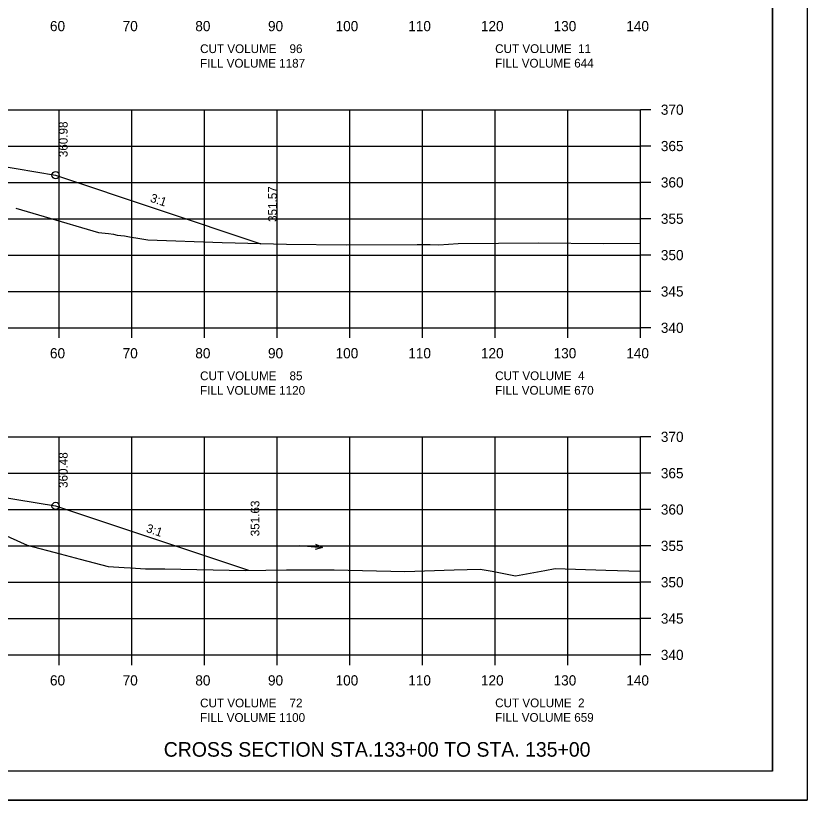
# Model space of a CAD drawing. Extents: x 1374859 to 1376773, y 382242 to 389804.
# Drawn here: x 1376188.6 to 1376297.5, y 385228.5 to 385336.4 of the extents above; entities that cross this region are included whole.
import ezdxf

# ---------------------------------------------------------------- set-up
doc = ezdxf.new("R2010")
doc.units = 0
for name, color, linetype in [('R_Axis', 7, 'Continuous'), ('R_Axis Annot', 7, 'Continuous'), ('R_Border', 7, 'Continuous'), ('R_Draft', 7, 'Continuous'), ('R_Exist Surface', 7, 'Continuous'), ('R_Fin Surface', 7, 'Continuous'), ('R_Grid', 7, 'Continuous'), ('R_No Plot', 7, 'Continuous'), ('R_Water Annot', 7, 'Continuous'), ('R_Xsect Elev', 7, 'Continuous'), ('R_Xsect Slope', 7, 'Continuous')]:
    doc.layers.add(name, color=color, linetype=linetype)

msp = doc.modelspace()

# ---------------------------------------------------------------- linework, layer by layer
at = {"layer": 'R_Axis'}
for p, q in [((1376274.57, 385293.45), (1376274.57, 385323.45)), ((1376275.97, 385323.45), (1376274.57, 385323.45)), ((1376275.97, 385318.45), (1376274.57, 385318.45)), ((1376275.97, 385313.45), (1376274.57, 385313.45)), ((1376275.97, 385308.45), (1376274.57, 385308.45)), ((1376275.97, 385303.45), (1376274.57, 385303.45)), ((1376275.97, 385298.45), (1376274.57, 385298.45)), ((1375994.57, 385293.45), (1376274.57, 385293.45)), ((1376194.57, 385292.05), (1376194.57, 385293.45)), ((1376204.57, 385292.05), (1376204.57, 385293.45)), ((1376214.57, 385292.05), (1376214.57, 385293.45)), ((1376224.57, 385292.05), (1376224.57, 385293.45)), ((1376234.57, 385292.05), (1376234.57, 385293.45)), ((1376244.57, 385292.05), (1376244.57, 385293.45)), ((1376254.57, 385292.05), (1376254.57, 385293.45)), ((1376264.57, 385292.05), (1376264.57, 385293.45)), ((1376274.57, 385292.05), (1376274.57, 385293.45)), ((1376275.97, 385293.45), (1376274.57, 385293.45)), ((1376274.57, 385248.45), (1376274.57, 385278.45)), ((1376275.97, 385278.45), (1376274.57, 385278.45)), ((1376275.97, 385273.45), (1376274.57, 385273.45)), ((1376275.97, 385268.45), (1376274.57, 385268.45)), ((1376275.97, 385263.45), (1376274.57, 385263.45)), ((1376275.97, 385258.45), (1376274.57, 385258.45)), ((1376275.97, 385253.45), (1376274.57, 385253.45)), ((1375994.57, 385248.45), (1376274.57, 385248.45)), ((1376194.57, 385247.05), (1376194.57, 385248.45)), ((1376204.57, 385247.05), (1376204.57, 385248.45)), ((1376214.57, 385247.05), (1376214.57, 385248.45)), ((1376224.57, 385247.05), (1376224.57, 385248.45)), ((1376234.57, 385247.05), (1376234.57, 385248.45)), ((1376244.57, 385247.05), (1376244.57, 385248.45)), ((1376254.57, 385247.05), (1376254.57, 385248.45)), ((1376264.57, 385247.05), (1376264.57, 385248.45)), ((1376274.57, 385247.05), (1376274.57, 385248.45)), ((1376275.97, 385248.45), (1376274.57, 385248.45))]:
    msp.add_line(p, q, dxfattribs=at)
at = {"layer": 'R_Border'}
for q in [(1376292.75, 385437.91), (1375976.57, 385232.45)]:
    msp.add_line((1376292.75, 385232.45), q, dxfattribs=at)
at = {"layer": 'R_Exist Surface'}
for points in [[(1376188.61, 385309.91), (1376192.52, 385308.77), (1376199.99, 385306.57), (1376201.36, 385306.41), (1376202.05, 385306.33), (1376202.07, 385306.32), (1376202.54, 385306.2), (1376203.57, 385306.09), (1376204.27, 385305.94), (1376205.66, 385305.72), (1376206.78, 385305.54), (1376217.01, 385305.16), (1376225.87, 385304.93), (1376234.08, 385304.88), (1376243.83, 385304.91), (1376245.61, 385304.89), (1376246.84, 385304.88), (1376249.46, 385305.03), (1376260.6, 385305.12), (1376269.44, 385305.04), (1376274.57, 385305.07)], [(1376178.83, 385268.64), (1376190.16, 385263.53), (1376194.72, 385262.35), (1376197.47, 385261.63), (1376201.3, 385260.59), (1376203.51, 385260.47), (1376204.41, 385260.42), (1376206.47, 385260.31), (1376209.11, 385260.27), (1376220.16, 385260.08), (1376225.87, 385260.17), (1376232.41, 385260.16), (1376242.14, 385259.91), (1376248.94, 385260.15), (1376252.52, 385260.25), (1376254.14, 385259.96), (1376257.38, 385259.33), (1376261.4, 385260.07), (1376262.84, 385260.34), (1376269.8, 385260.13), (1376274.57, 385259.98)]]:
    msp.add_lwpolyline(points, dxfattribs=at)
at = {"layer": 'R_Fin Surface'}
for points in [[(1376049.29, 385304.98), (1376056.66, 385302.52), (1376075.09, 385308.66), (1376083.13, 385310), (1376097.09, 385312.33), (1376105.09, 385312.95), (1376134.59, 385315.22), (1376164.09, 385317.49), (1376172.09, 385318.1), (1376185.9, 385315.8), (1376194.09, 385314.44), (1376222.34, 385305.02)], [(1376051.43, 385259.78), (1376058.18, 385257.53), (1376075.09, 385263.16), (1376083.13, 385264.5), (1376097.09, 385266.83), (1376105.09, 385267.45), (1376134.59, 385269.72), (1376164.09, 385271.99), (1376172.09, 385272.6), (1376185.9, 385270.3), (1376194.09, 385268.94), (1376220.64, 385260.09)]]:
    msp.add_lwpolyline(points, dxfattribs=at)
at = {"layer": 'R_Grid'}
for p, q in [((1375994.57, 385323.45), (1376274.57, 385323.45)), ((1376194.57, 385293.45), (1376194.57, 385323.45)), ((1376204.57, 385293.45), (1376204.57, 385323.45)), ((1376214.57, 385293.45), (1376214.57, 385323.45)), ((1376224.57, 385293.45), (1376224.57, 385323.45)), ((1376234.57, 385293.45), (1376234.57, 385323.45)), ((1376244.57, 385293.45), (1376244.57, 385323.45)), ((1376254.57, 385293.45), (1376254.57, 385323.45)), ((1376264.57, 385293.45), (1376264.57, 385323.45)), ((1376274.57, 385293.45), (1376274.57, 385323.45)), ((1375994.57, 385318.45), (1376274.57, 385318.45)), ((1375994.57, 385313.45), (1376274.57, 385313.45)), ((1375994.57, 385308.45), (1376274.57, 385308.45)), ((1375994.57, 385303.45), (1376274.57, 385303.45)), ((1375994.57, 385298.45), (1376274.57, 385298.45)), ((1375994.57, 385293.45), (1376274.57, 385293.45)), ((1375994.57, 385278.45), (1376274.57, 385278.45)), ((1376194.57, 385248.45), (1376194.57, 385278.45)), ((1376204.57, 385248.45), (1376204.57, 385278.45)), ((1376214.57, 385248.45), (1376214.57, 385278.45)), ((1376224.57, 385248.45), (1376224.57, 385278.45)), ((1376234.57, 385248.45), (1376234.57, 385278.45)), ((1376244.57, 385248.45), (1376244.57, 385278.45)), ((1376254.57, 385248.45), (1376254.57, 385278.45)), ((1376264.57, 385248.45), (1376264.57, 385278.45)), ((1376274.57, 385248.45), (1376274.57, 385278.45)), ((1375994.57, 385273.45), (1376274.57, 385273.45)), ((1375994.57, 385268.45), (1376274.57, 385268.45)), ((1375994.57, 385263.45), (1376274.57, 385263.45)), ((1375994.57, 385258.45), (1376274.57, 385258.45)), ((1375994.57, 385253.45), (1376274.57, 385253.45)), ((1375994.57, 385248.45), (1376274.57, 385248.45))]:
    msp.add_line(p, q, dxfattribs=at)
at = {"layer": 'R_No Plot'}
msp.add_line((1375964.17, 385228.47), (1376297.5, 385228.47), dxfattribs=at)
for points in [[(1375964.16, 385441.81), (1376297.5, 385441.81), (1376297.5, 385228.47), (1375964.16, 385228.47)], [(1376210.49, 385437.91), (1376210.49, 385428.03), (1376246.22, 385428.03), (1376246.22, 385425.11), (1376269.42, 385425.11), (1376269.42, 385400.78), (1376292.75, 385400.78), (1376292.75, 385232.45), (1375976.57, 385232.45), (1375976.57, 385437.91)]]:
    msp.add_lwpolyline(points, close=True, dxfattribs=at)
for centre in [(1376194.09, 385314.44), (1376194.09, 385268.94)]:
    msp.add_circle(centre, 0.5, dxfattribs=at)
at = {"layer": 'R_Water Annot'}
for p, q in [((1376227.68, 385263.52), (1376230.81, 385263.21)), ((1376230.81, 385263.21), (1376229.82, 385262.96)), ((1376230.81, 385263.21), (1376229.88, 385263.66))]:
    msp.add_line(p, q, dxfattribs=at)

# ---------------------------------------------------------------- texts
at = {"layer": 'R_Axis Annot'}
for s, height, p in [('60', 1.4, (1376193.31, 385334.25)), ('70', 1.4, (1376203.31, 385334.25)), ('80', 1.4, (1376213.31, 385334.25)), ('90', 1.4, (1376223.31, 385334.25)), ('100', 1.4, (1376232.61, 385334.25)), ('110', 1.4, (1376242.61, 385334.25)), ('120', 1.4, (1376252.61, 385334.25)), ('130', 1.4, (1376262.61, 385334.25)), ('140', 1.4, (1376272.61, 385334.25)), ('CUT VOLUME    96', 1.2, (1376213.97, 385331.24)), ('CUT VOLUME  11', 1.2, (1376254.57, 385331.25)), ('FILL VOLUME 1187', 1.2, (1376213.97, 385329.24)), ('FILL VOLUME 644', 1.2, (1376254.57, 385329.25)), ('370', 1.4, (1376277.37, 385322.75)), ('365', 1.4, (1376277.37, 385317.75)), ('360', 1.4, (1376277.37, 385312.75)), ('355', 1.4, (1376277.37, 385307.75)), ('350', 1.4, (1376277.37, 385302.75)), ('345', 1.4, (1376277.37, 385297.75)), ('340', 1.4, (1376277.37, 385292.75)), ('60', 1.4, (1376193.31, 385289.25)), ('70', 1.4, (1376203.31, 385289.25)), ('80', 1.4, (1376213.31, 385289.25)), ('90', 1.4, (1376223.31, 385289.25)), ('100', 1.4, (1376232.61, 385289.25)), ('110', 1.4, (1376242.61, 385289.25)), ('120', 1.4, (1376252.61, 385289.25)), ('130', 1.4, (1376262.61, 385289.25)), ('140', 1.4, (1376272.61, 385289.25)), ('CUT VOLUME    85', 1.2, (1376213.97, 385286.24)), ('CUT VOLUME  4', 1.2, (1376254.57, 385286.25)), ('FILL VOLUME 1120', 1.2, (1376213.97, 385284.24)), ('FILL VOLUME 670', 1.2, (1376254.57, 385284.25)), ('370', 1.4, (1376277.37, 385277.75)), ('365', 1.4, (1376277.37, 385272.75)), ('360', 1.4, (1376277.37, 385267.75)), ('355', 1.4, (1376277.37, 385262.75)), ('350', 1.4, (1376277.37, 385257.75)), ('345', 1.4, (1376277.37, 385252.75)), ('340', 1.4, (1376277.37, 385247.75)), ('60', 1.4, (1376193.31, 385244.25)), ('70', 1.4, (1376203.31, 385244.25)), ('80', 1.4, (1376213.31, 385244.25)), ('90', 1.4, (1376223.31, 385244.25)), ('100', 1.4, (1376232.61, 385244.25)), ('110', 1.4, (1376242.61, 385244.25)), ('120', 1.4, (1376252.61, 385244.25)), ('130', 1.4, (1376262.61, 385244.25)), ('140', 1.4, (1376272.61, 385244.25)), ('CUT VOLUME    72', 1.2, (1376213.97, 385241.24)), ('CUT VOLUME  2', 1.2, (1376254.57, 385241.25)), ('FILL VOLUME 1100', 1.2, (1376213.97, 385239.24)), ('FILL VOLUME 659', 1.2, (1376254.57, 385239.25))]:
    msp.add_text(s, height=height, dxfattribs=at).set_placement(p)
at = {"layer": 'R_Draft'}
msp.add_text('CROSS SECTION STA.133+00 TO STA. 135+00', height=2, dxfattribs=at).set_placement((1376208.97, 385234.45))
at = {"layer": 'R_Xsect Elev'}
for s, p in [('360.98', (1376195.74, 385316.92)), ('351.57', (1376224.53, 385308.01)), ('360.48', (1376195.74, 385271.42)), ('351.63', (1376222.13, 385264.77))]:
    msp.add_text(s, height=1.2, rotation=90, dxfattribs=at).set_placement(p)
at = {"layer": 'R_Xsect Slope'}
for p in [(1376207.01, 385310.82), (1376206.45, 385265.38)]:
    msp.add_text('3:1', height=1.2, rotation=341.5651, dxfattribs=at).set_placement(p)

doc.saveas('drawing.dxf')
